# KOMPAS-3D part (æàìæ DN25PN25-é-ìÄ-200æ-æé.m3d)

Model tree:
1. Объединить компоненты:1  (labels: СЕНС DN25PN25-В-НО-200С)
2. Эскиз:1
3. Операция выдавливания:1
     Расстояние 1 = 14
4. Фаска:1
     Угол = 45; Длина 1 = 2; Длина 2 = 2

Referenced files in D:\Савин\!СЕНСОР\3D для заказчика\!Новый перечень\СЕНС\7. СЕНС-В-НО-200С\DN25\: СЕНС DN25PN25-В-НО-200С.a3d
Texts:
  СЕНС DN25PN25-В-НО-200С-СВ
  ООО НПП Сенсор
  СЕНС DN25PN25-В-НО-200С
